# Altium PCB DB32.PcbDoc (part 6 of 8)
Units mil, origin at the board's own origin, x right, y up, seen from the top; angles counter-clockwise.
Board outline 3236.22 x 4456.69 mil, 8 copper layers (Top Layer, MidLayer1, MidLayer2, GND-Layer5, MidLayer3, VCC, MidLayer4, Bottom Layer), stack 61.8 mil thick; 207 components, 474 nets, 1777 pads, 1474 vias.
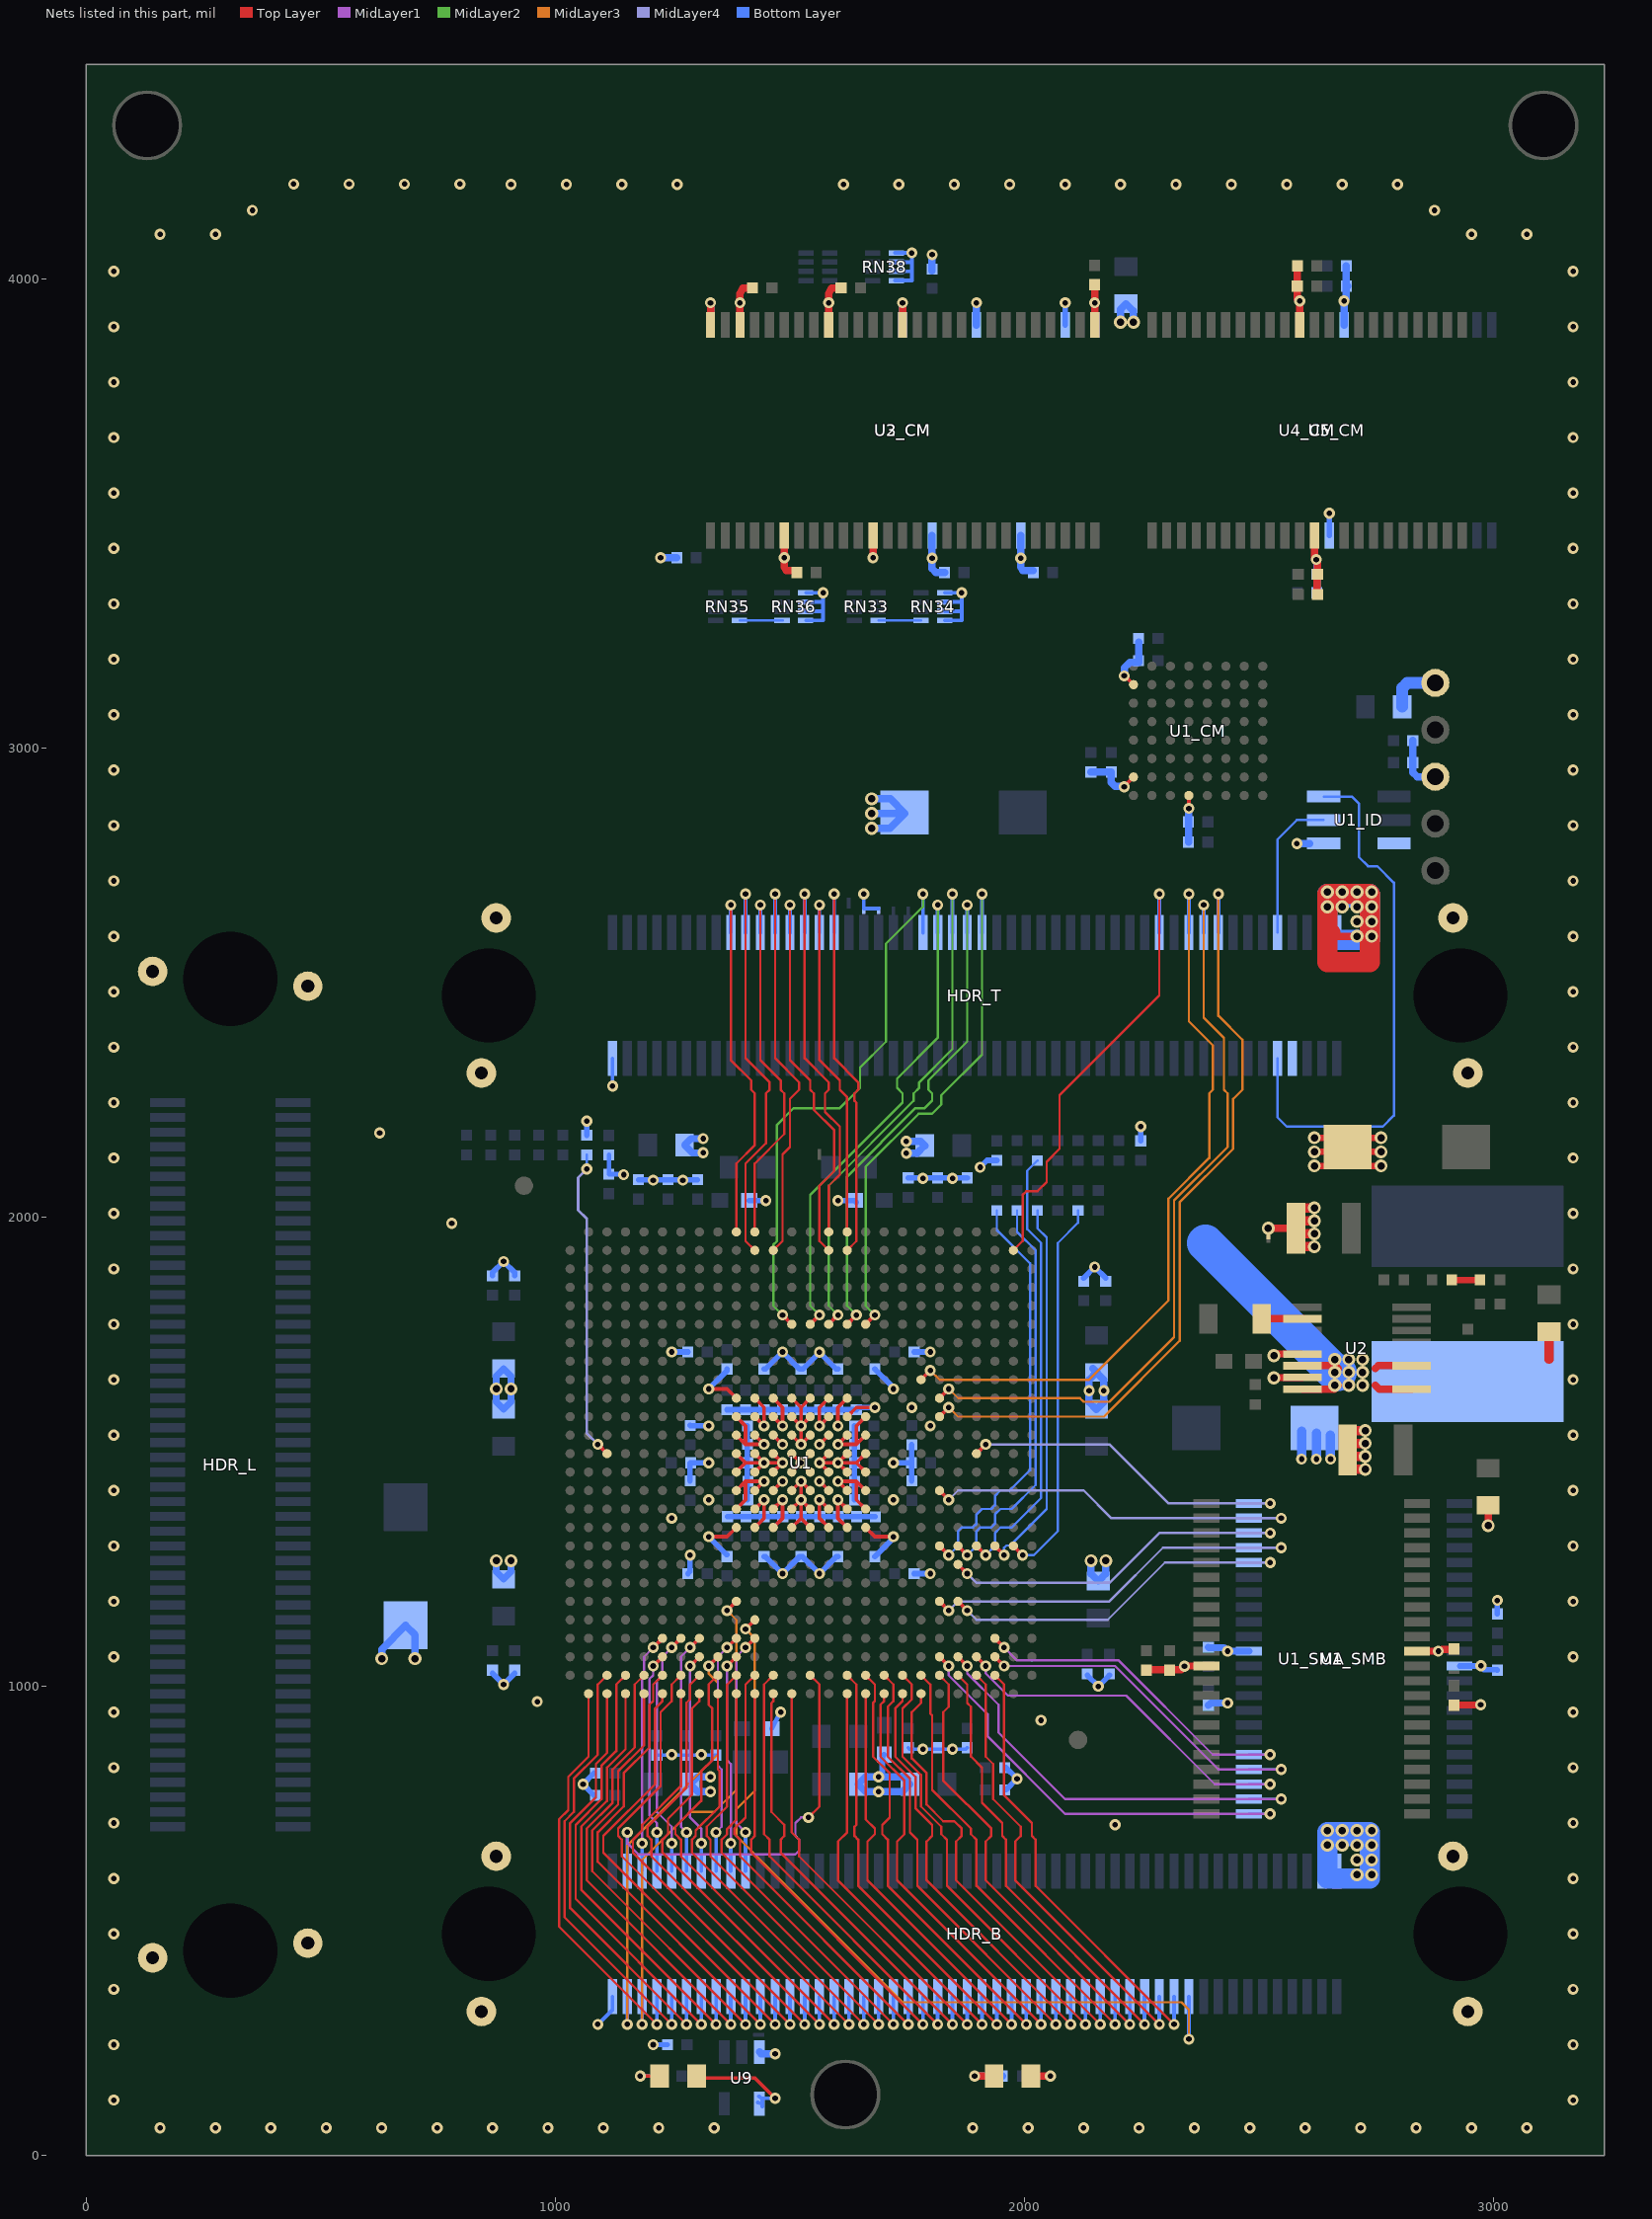
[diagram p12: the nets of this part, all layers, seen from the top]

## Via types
v1: diameter 23.62, hole 11.81, Top Layer to Bottom Layer, 839 vias
v2: diameter 23.62, hole 11.81, Top Layer to Bottom Layer, tented both sides, 499 vias
v3: diameter 27.56, hole 15.75, Top Layer to Bottom Layer, 135 vias
v4: diameter 23.62, hole 11.81, Top Layer to Bottom Layer, tented top, 1 vias

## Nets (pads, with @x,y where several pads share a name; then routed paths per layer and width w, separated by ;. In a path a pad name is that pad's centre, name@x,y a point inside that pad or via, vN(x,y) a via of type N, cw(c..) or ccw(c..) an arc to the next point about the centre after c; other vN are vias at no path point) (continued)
GND: C1_CM.2 C1_FP.2 C1_ID.1 C1_MB.2 C1_PL.2 C1_SMA.2 C1_SMB.2 C2_CM.2 C2_FP.2 C2_ID.2 C2_MB.2 C2_PL.2 C2_SMA.2 C2_SMB.2 C3_CM.2 C3_FP.2 C3_PL.2 C3_SMA.2 C3_SMB.2 C4_CM.2 C4_FP.2 C4_PL.2 C4_SMA.2 C4_SMB.2 C5_CM.2 C5_FP.2 C5_MB.2 C5_PL.2 C6_CM.2 C6_FP.2 C6_PL.2 C7_CM.2 C7_FP.2 C7_PL.2 C8_CM.2 C8_FP.2 C8_PL.2 C9_CM.2 C9_FP.2 C9_PL.2 C10_CM.2 C10_FP.2 C10_PL.2 C11_CM.2 C11_FP.2 C11_PL.2 C12_CM.2 C12_FP.2 C12_PL.2 C13_CM.2 C13_PL.2 C14_CM.2 C14_PL.2 C15.2 C15_CM.2 C15_FP.2 C15_PL.2 C16_CM.2 C16_FP.2 C16_PL.2 C17.2 C17_CM.2 C17_FP.2 C18_CM.2 C18_FP.2 C19.2 C19_CM.2 C19_FP.2 C20.2 C20_CM.2 C20_FP.2 C21_CM.2 C21_FP.2 C22.2 C22_CM.2 C22_FP.2 C23_CM.2 C23_FP.2 C24_CM.2 C24_FP.2 C25_FP.2 C38_FP.2 C39_FP.2 C40_FP.2 C41_FP.2 C42_FP.2 C43_FP.2 C44_FP.2 C45_FP.2 C46_FP.2 C47_FP.2 C48_FP.2 C49_FP.2 C50_FP.2 C51_FP.2 C52_FP.2 C53_FP.2 C54_FP.2 C55_FP.2 C56_FP.2 C62_FP.2 C63_FP.2 C64_FP.2 C65_FP.2 C66_FP.2 C67_FP.2 C68_FP.2 C69_FP.2 C70_FP.2 C71_FP.2 C72_FP.2 C73_FP.2 C74_FP.2 C75_FP.2 C76_FP.2 C77_FP.2 C78_FP.2 C79_FP.2 C80_FP.2 C81_FP.2 C82_FP.2 C83_FP.2 C84_FP.2 C85_FP.2 C86_FP.2 C87_FP.2 C88_FP.2 C89_FP.2 C90_FP.2 C91_FP.2 C92_FP.2 C93_FP.2 C98.1 HDR_B.1 HDR_B.98 HDR_B.100 HDR_B.MH1 HDR_B.MH2 HDR_B.MH3 HDR_B.MH4 HDR_L.MH1 HDR_L.MH2 HDR_L.MH3 HDR_L.MH4 HDR_T.1 HDR_T.98 HDR_T.100 HDR_T.MH1 HDR_T.MH2 HDR_T.MH3 HDR_T.MH4 LED1.2 NT4.2 NT5.2 NT7.2 R5.2 RN34.1 RN34.2 RN34.3 RN34.4 RN36.1 RN36.2 RN36.3 RN36.4 RN38.1 RN38.2 RN38.3 RN38.4 TP0.1 TP2.1 U1.K10 U1.K11 U1.K12 U1.K13 U1.K14 U1.K15 U1.K16 U1.L10 U1.L11 U1.L12 U1.L13 U1.L14 U1.L15 U1.L16 U1.L17 U1.M10 U1.M11 U1.M12 U1.M13 U1.M14 U1.M15 U1.M16 U1.M17 U1.N10 U1.N11 U1.N12 U1.N13 U1.N14 U1.N15 U1.N16 U1.N17 U1.P10 U1.P11 U1.P12 U1.P13 U1.P14 U1.P15 U1.P16 U1.P17 U1.R10 U1.R11 U1.R12 U1.R13 U1.R14 U1.R15 U1.R16 U1.R17 U1.T10 U1.T11 U1.T12 U1.T13 U1.T14 U1.T15 U1.T16 U1.T17 U1.U10 U1.U11 U1.U12 U1.U13 U1.U14 U1.U15 U1.U16 U1.U17 U1_CM.E8 U1_CM.H2 U1_CM.H7 U1_ID.1 U1_SMA.12 U1_SMA.34 U1_SMB.12 U1_SMB.34 U2.13 U2.15 U2_CM.6 U2_CM.12 U2_CM.28 U2_CM.41 U2_CM.46 U2_CM.52 U2_CM.54 U3_CM.6 U3_CM.12 U3_CM.28 U3_CM.41 U3_CM.46 U3_CM.52 U3_CM.54 U4_CM.12 U4_CM.34 U5_CM.12 U5_CM.34 U9.3 | length 14104.8
  Top Layer w7.87: v1(1326.77,1318.9) 1366.14,1318.9 U1.U10@1385.83,1338.58 ; v1(1326.77,1633.86) 1366.14,1633.86 U1.K10@1385.83,1614.17 ; U1.T10@1385.83,1377.95 1405.51,1397.64 1405.51,1437.01 ; U1.R10@1385.83,1417.32 1405.51,1437.01 ; U1.P10@1385.83,1456.69 1405.51,1476.38 ; U1.N10@1385.83,1496.06 1405.51,1476.38 ; U1.M10@1385.83,1535.43 1405.51,1515.75 ; U1.L10@1385.83,1574.8 1405.51,1555.12 1405.51,1515.75 ; U1.U11@1425.2,1338.58 1444.88,1358.27 v1(1444.88,1397.64) U1.T11@1425.2,1377.95 ; U1.R11@1425.2,1417.32 v1(1444.88,1437.01) 1405.51,1437.01 ; U1.P11@1425.2,1456.69 v1(1444.88,1476.38) ; U1.N11@1425.2,1496.06 v1@1444.88,1476.38 ; U1.M11@1425.2,1535.43 v1(1444.88,1515.75) 1405.51,1515.75 ; U1.L11@1425.2,1574.8 v1(1444.88,1555.12) 1444.88,1594.49 U1.K11@1425.2,1614.17 ; U1.U12@1464.57,1338.58 1484.25,1358.27 v1(1484.25,1397.64) U1.T12@1464.57,1377.95 ; U1.R12@1464.57,1417.32 v1(1484.25,1437.01) ; U1.P12@1464.57,1456.69 v1(1484.25,1476.38) ; U1.N12@1464.57,1496.06 v1(1484.25,1476.38) ; U1.M12@1464.57,1535.43 v1(1484.25,1515.75) ; U1.L12@1464.57,1574.8 v1(1484.25,1555.12) 1484.25,1594.49 U1.K12@1464.57,1614.17 ; U1.R13@1503.94,1417.32 v1(1523.62,1437.01) ; U1.P13@1503.94,1456.69 U1.N14@1543.31,1496.06 ; U1.N13@1503.94,1496.06 U1.P14@1543.31,1456.69 ; U1.M13@1503.94,1535.43 v1(1523.62,1515.75) ; U1.L13@1503.94,1574.8 v1(1523.62,1555.12) U1.L14@1543.31,1574.8 ; U1.K13@1503.94,1614.17 1523.62,1594.49 ; U1.U14@1543.31,1338.58 1523.62,1358.27 ; U1.T14@1543.31,1377.95 v1(1523.62,1397.64) ; U1.R14@1543.31,1417.32 v1(1523.62,1437.01) ; U1.M14@1543.31,1535.43 v1(1523.62,1515.75) ; U1.K14@1543.31,1614.17 1523.62,1594.49 ; v1(1562.99,1437.01) U1.R15@1582.68,1417.32 ; v1(1562.99,1515.75) U1.M15@1582.68,1535.43 ; U1.U15@1582.68,1338.58 1562.99,1358.27 v1(1562.99,1397.64) U1.T15@1582.68,1377.95 ; U1.P15@1582.68,1456.69 v1(1562.99,1476.38) ; U1.N15@1582.68,1496.06 v1(1562.99,1476.38) ; U1.L15@1582.68,1574.8 v1(1562.99,1555.12) 1562.99,1594.49 U1.K15@1582.68,1614.17 ; v1(1602.36,1555.12) 1602.36,1594.49 U1.K16@1622.05,1614.17 ; U1.U16@1622.05,1338.58 1602.36,1358.27 v1(1602.36,1397.64) U1.T16@1622.05,1377.95 ; U1.R16@1622.05,1417.32 v1(1602.36,1437.01) 1641.73,1437.01 ; U1.P16@1622.05,1456.69 v1(1602.36,1476.38) ; U1.N16@1622.05,1496.06 v1@1602.36,1476.38 ; U1.M16@1622.05,1535.43 v1(1602.36,1515.75) 1641.73,1515.75 ; U1.L16@1622.05,1574.8 1641.73,1594.49 v1(1681.1,1594.49) ; U1.U17@1661.42,1338.58 1681.1,1318.9 v1(1720.47,1318.9) ; U1.T17@1661.42,1377.95 1641.73,1397.64 1641.73,1437.01 ; U1.R17@1661.42,1417.32 1641.73,1437.01 ; U1.P17@1661.42,1456.69 1641.73,1476.38 ; U1.N17@1661.42,1496.06 1641.73,1476.38 ; U1.M17@1661.42,1535.43 1641.73,1515.75 ; U1.L17@1661.42,1574.8 1641.73,1555.12 1641.73,1515.75 ; v1@2212.6,2918.31 U1_CM.H7@2232.28,2937.99 ; v1@2212.6,3154.53 U1_CM.H2@2232.28,3134.84 ; v1(2350.4,2871.07) U1_CM.E8@2350.39,2898.62 ; 1405.51,1476.38 v1(1444.88,1476.38) ; 1405.51,1476.38 v1@1444.88,1476.38 ; v1@1444.88,1476.38 v1(1484.25,1476.38) ; 1523.62,1358.27 v1(1523.62,1397.64) ; 1523.62,1358.27 U1.U13@1503.94,1338.58 1523.62,1358.27 ; v1(1523.62,1397.64) U1.T13@1503.94,1377.95 v1(1523.62,1397.64) ; v1(1523.62,1397.64) v1(1523.62,1437.01) ; v1(1523.62,1515.75) 1523.62,1594.49 ; v1(1562.99,1476.38) 1641.73,1476.38 ; v1@1602.36,1476.38 1641.73,1476.38
  Top Layer w13.78: v3(2618.11,2109.29) C17.2@2669.08,2109.29 ; v3(2618.11,2139.29) C17.2@2669.08,2139.29 ; v3(2618.11,2169.29) 2669.08,2169.29 C17.2@2689.05,2149.33 C17.2@2673.58,2133.85 ; C17.2@2709.01,2109.29 v3(2759.99,2109.29) ; C17.2@2709.01,2139.29 v3(2759.99,2139.29) ; C17.2@2709.01,2169.29 v3(2759.99,2169.29)
  Top Layer w15: C4_SMA.2@2259.84,1034.45 2260.82,1035.43 2334.65,1035.43 2341,1041.79 v1(2341,1043) 2341.3,1043.3 U1_SMA.34@2387.87,1043.31 ; v3(2531.5,1657.48) 2532.26,1658.25 U2.15@2591.08,1658.25 ; v3(2531.5,1704.72) 2535.43,1708.66 U2.13@2590.55,1708.66 ; U1_SMA.12@2836.69,1074.8 2881.8,1074.8 v1(2882,1075) 2886.02,1075 2889.76,1078.74 2914.47,1078.74 C1_SMA.2@2915.44,1079.71 ; C3_SMA.2@2915.3,957.92 2917.32,957.76 2914.45,960.63 v1(2972.44,960.63)
  Top Layer w15.75: U2_CM.54@1330.71,3901.57 v2(1330.71,3948.82) ; U2_CM.52@1393.7,3901.57 v2(1393.7,3948.82) ; v2@1393.7,3944.88 1393.7,3964.57 ; 1393.7,3968.51 1399.61,3980.32 C7_CM.2@1420.27,3980.31 ; C7_CM.2@1416.34,3980.32 C7_CM.2@1418.31,3978.34 ; U2_CM.6@1488.19,3452.76 1488.19,3409.45 v2(1488.19,3405.51) 1488.19,3385.83 1492.13,3377.95 C10_CM.2@1514.76,3377.95 ; U2_CM.46@1582.68,3901.57 v2(1582.68,3948.82) ; v2@1582.68,3944.88 1582.68,3964.57 1582.68,3968.51 1588.58,3980.32 C8_CM.2@1609.25,3980.31 ; v2(1677.17,3405.51) U2_CM.12@1677.17,3452.76 ; U2_CM.41@1740.16,3901.57 v2(1740.16,3948.82) ; LED1.2@2011.81,169.29 v1(2055.12,169.29) ; U2_CM.28@2149.61,3901.57 C9_CM.2@2149.6,3987.2 ; v3(2519.68,1976.38) C15.2@2582.67,1976.38 ; C16_CM.2@2581.69,4027.55 2581.69,3957.68 v2(2586.61,3952.76) U4_CM.34@2586.61,3901.57 ; U4_CM.12@2618.11,3452.76 2618.11,3405.51 2624.72,3398.9 C17_CM.2@2624.72,3370.07 C17_CM.2@2625.71,3371.06 ; C15_CM.2@2623.74,3329.72 C17_CM.2@2623.74,3370.07 ; 2645.67,2598.43 v3(2708.66,2598.43) ; v3(2988.19,1342.52) C19.2@2988.18,1385.82
  Top Layer w19.68: 2645.67,2551.18 2649.61,2555.12 ; 3118.09,1696.83 C22.2@3118.1,1755.9
  Top Layer w20: C15.2@2578.73,1937 v3(2618.1,1937) ; C15.2@2578.73,1964.56 v3(2618.1,1964.56) ; C15.2@2578.73,1992.12 v3(2618.1,1992.12) ; C15.2@2578.73,2019.68 v3(2618.1,2019.68) ; C20.2@2687.01,1462.59 v3(2726.38,1462.59) ; C20.2@2687.01,1490.15 v3(2726.38,1490.15) ; C20.2@2687.01,1517.71 v3(2726.38,1517.71) ; C20.2@2687.01,1545.27 v3(2726.38,1545.27)
  Top Layer w39.37: 2645.67,2606.3 2653.54,2606.3
  Top Layer w43.31: 2645.67,2547.24 2649.61,2543.31 ; 2645.67,2543.31 2736.22,2543.31 2736.22,2688.98 2645.67,2688.98 2645.67,2543.31
  Bottom Layer w5: v2@1121.06,2278.54 v2(1122.05,2279.53)
  Bottom Layer w7.87: v2(1090.55,279.53) 1122.05,311.02 HDR_B.1@1122.05,338.58 ; v2(1122.05,2279.53) HDR_T.1@1122.05,2338.58 ; C4_PL.2@1216.53,853.34 C2_PL.2@1342.52,853.34 ; RN36.4@1534.64,3271.65 1570.87,3271.65 v1(1570.87,3330.71) RN36.1@1534.64,3330.71 ; RN36.3@1534.64,3291.34 1570.87,3291.34 ; RN36.2@1534.64,3311.02 1570.87,3311.02 ; v2(1657.48,2688.98) 1657.48,2657.48 NT4.2@1688.98,2657.48 ; RN38.4@1723.62,3996.06 1759.84,3996.06 v1(1759.84,4055.12) RN38.1@1723.62,4055.12 ; RN38.3@1723.62,4015.75 1759.84,4015.75 ; RN38.2@1723.62,4035.43 1759.84,4035.43 ; C14_PL.2@1751.97,869.09 1754.92,866.14 1875,866.14 C16_PL.2@1877.95,869.09 ; RN34.4@1829.92,3271.65 1866.14,3271.65 v1(1866.14,3330.71) RN34.1@1829.92,3330.71 ; RN34.3@1829.92,3291.34 1866.14,3291.34 ; RN34.2@1829.92,3311.02 1866.14,3311.02
  Bottom Layer w9.84: C81_FP.2@1114.17,2132.87 C80_FP.2@1114.17,2091.53 1144.69,2091.53 v1(1145.67,2090.55) ; v1(1208.66,236.22) C98.1@1239.17,236.22 ; C1_PL.2@1460.63,909.45 v1(1480.31,944.88)
  Bottom Layer w11.81: C85_FP.2@866.14,1027.56 v2(889.76,1003.94) C84_FP.2@913.39,1027.56 ; C82_FP.2@866.14,1875 866.14,1881.89 v2(889.76,1905.51) 913.38,1881.89 C83_FP.2@913.38,1875 ; R5.2@1066.93,2174.72 v1(1066.93,2204.72) ; C86_FP.2@1082.68,767.71 v2(1059.06,791.34) C87_FP.2@1082.68,814.96 ; C12_PL.2@1177.16,2079.72 C10_PL.2@1303.15,2079.72 ; v1(1248.03,1712.6) C19_FP.2@1282.48,1712.59 ; C4_FP.2@1282.48,1240.16 1287.4,1245.08 v1(1287.4,1279.53) ; C15_FP.2@1287.4,1437.99 1287.4,1475.39 C24_FP.2@1288.38,1476.37 v1@1326.77,1476.37 ; C25_FP.2@1287.4,1556.1 1288.38,1555.12 v1(1326.77,1555.12) ; v1(1326.77,1318.9) 1365.16,1280.51 C16_FP.2@1366.14,1280.51 ; v1(1326.77,1633.86) 1366.14,1673.23 C12_FP.2@1366.14,1676.18 ; C69_FP.2@1366.14,1589.56 C64_FP.2@1641.73,1589.56 1646.65,1594.49 v1(1681.1,1594.49) ; C73_FP.2@1366.82,1361.64 C63_FP.2@1681.78,1361.64 ; C65_FP.2@1409.45,1397.63 C54_FP.2@1409.45,1555.12 ; C9_PL.2@1417.33,2035.43 C9_PL.2@1413.39,2035.43 v1(1448.82,2035.43) ; C5_FP.2@1444.88,1276.57 1447.84,1276.57 v1(1484.25,1240.16) 1520.67,1276.57 1526.58,1276.57 v1(1562.99,1240.16) 1599.41,1276.57 C6_FP.2@1602.36,1276.57 ; C23_FP.2@1444.88,1676.18 1447.83,1676.18 v1(1484.25,1712.6) 1520.67,1676.18 1527.16,1676.18 v1(1562.99,1712.01) 1598.82,1676.18 C22_FP.2@1602.36,1676.18 ; v1(1602.36,2035.43) C5_PL.2@1637.79,2035.43 ; C5_PL.2@1629.92,2035.43 C5_PL.2@1637.79,2035.43 ; C76_FP.2@1637.8,1397.64 C56_FP.2@1637.8,1555.12 ; C5_PL.2@1641.73,2031.49 C5_PL.2@1637.79,2035.43 ; C18_FP.2@1681.1,1276.57 1720.47,1315.95 v1(1720.47,1318.9) ; C10_FP.2@1681.1,1676.18 1720.47,1636.8 v1(1720.47,1633.86) ; v1(1688.98,807.09) 1696.85,814.96 1696.85,850.39 C13_PL.2@1700.78,854.33 ; v1(1720.47,1476.38) C20_FP.2@1758.85,1476.38 ; C6_PL.2@1751.97,2083.66 C8_PL.2@1877.95,2083.66 ; C8_FP.2@1759.84,1437.99 1759.84,1475.39 C20_FP.2@1758.85,1476.37 ; C9_FP.2@1759.84,1514.76 1759.84,1477.36 C20_FP.2@1758.85,1476.37 ; C7_FP.2@1764.76,1240.16 v1(1799.21,1240.16) ; C21_FP.2@1764.76,1712.6 v1(1799.21,1712.6) ; v2(1905.51,2106.3) 1920.27,2121.06 C79_FP.2@1940.94,2121.06 ; C88_FP.2@1960.63,779.53 v2(1984.25,803.15) C89_FP.2@1960.63,826.77 ; U3_CM.52@2086.61,3901.57 v2(2086.61,3948.82) ; C93_FP.2@2125.98,1870.08 v2(2149.61,1893.7) C92_FP.2@2173.23,1870.08 ; C91_FP.2@2133.86,1023.62 v2(2157.48,1000) C90_FP.2@2181.1,1023.62 ; U3_CM.54@2149.61,3901.57 v2(2149.61,3948.82) ; C78_FP.2@2248.03,2162.4 v2(2248.03,2192.91) ; U5_CM.12@2649.61,3452.76 v2(2649.61,3500) ; U1_SMB.34@2927.25,1043.3 v1@2972.3,1043.3 ; v1(2973,1044) v1@2972.3,1043.3 ; C4_SMB.2@3007.87,1034.45 3006.88,1035.43 2979.33,1035.43 2972.3,1042.47 v1@2972.3,1043.3 ; C2_SMB.2@3007.87,1154.53 v1(3007.87,1183.07)
  Bottom Layer w15: C1_MB.2@661.42,1110.59 C1_MB.2@680.83,1130 700.79,1110.04 v3(700.79,1059.06) ; v3(874.02,1267.72) 874.02,1244.09 C41_FP.2@889.76,1228.34 905.51,1244.09 v3(905.51,1267.72) ; v1@1314.96,2137.14 1291.99,2137.14 C38_FP.2@1275.59,2153.54 1289.29,2167.24 v1(1315.08,2167.24) ; v2(1330.71,775.59) 1303.15,775.59 C45_FP.2@1287.4,791.34 1303.15,807.09 v2(1330.71,807.09) ; v1@1748.03,2139.93 1748.03,2132.31 v1(1748.27,2136.26) ; v1(1748.27,2136.26) 1771.23,2136.24 C40_FP.2@1787.52,2152.54 ; C1_SMB.2@2391.82,959.64 2396.75,964.57 v1(2433.07,964.57) ; C3_SMB.2@2391.82,1083.65 2392.8,1082.68 2425.2,1082.68 v1@2432.87,1075 ; v1(2433,1075) 2433.21,1074.79 U1_SMB.12@2478.43,1074.8 ; C1_FP.2@874.02,1606.29 C1_FP.2@889.76,1590.55 905.51,1606.3 905.51,1661.41 C39_FP.2@889.76,1677.16 874.02,1661.42 C1_FP.2@874.02,1606.29 ; C2_FP.2@1645.67,791.34 1661.41,775.59 1740.16,775.59 C44_FP.2@1755.9,791.34 1740.15,807.09 1661.42,807.09 C2_FP.2@1645.67,791.34
  Bottom Layer w15.75: v3(629.92,1059.06) 629.92,1079.09 C1_MB.2@680.83,1130 ; v2(1224.41,3405.51) C13_CM.2@1258.85,3405.51 ; U3_CM.28@1330.71,3901.57 v2@1330.71,3944.88 ; U9.3@1435.04,220.47 1438.97,216.54 v1(1468.5,216.54) ; v3(1674.21,2828.74) 1713.39,2828.74 1745.15,2860.51 1713.93,2891.73 v3(1674.21,2891.73) ; v3(1674.21,2860.24) C2_MB.2@1744.88,2860.24 ; U3_CM.41@1740.16,3901.57 v2(1740.16,3948.82) ; v1(1748.03,2161.42) 1778.65,2161.42 C40_FP.2@1787.52,2152.54 ; U3_CM.12@1803.15,3452.76 1803.15,3405.51 v2(1803.15,3404.53) 1803.15,3381.89 1811.04,3374.01 C12_CM.2@1829.72,3374.01 ; C14_CM.2@1803.15,4016.72 1803.15,4047.24 v2(1803.15,4051.18) ; U3_CM.46@1897.64,3901.57 v2(1897.64,3948.82) v2@1897.64,3944.88 ; U3_CM.6@1992.13,3452.76 1992.13,3385.83 1996.06,3377.95 C11_CM.2@2018.7,3377.95 ; v3(2141.73,1267.72) 2141.73,1240.15 C43_FP.2@2157.48,1224.41 2161.42,1228.35 2173.23,1240.16 v3(2173.23,1267.72) ; C4_CM.2@2141.73,2948.82 C1_CM.2@2185.04,2948.82 2185.04,2926.19 2192.92,2918.31 v1@2212.6,2918.31 ; C42_FP.2@2145.66,1677.16 2169.29,1653.54 2169.29,1606.3 C3_FP.2@2153.54,1590.55 2137.8,1606.29 2137.8,1653.54 C42_FP.2@2153.54,1669.29 ; v3(2204.72,3907.48) 2204.72,3935.04 C24_CM.2@2216.53,3946.84 2232.28,3931.1 v3(2232.28,3907.48) ; v1(2212.6,3153.54) 2212.6,3170.28 2224.41,3182.09 2243.11,3182.09 C6_CM.2@2243.11,3225.39 ; C5_CM.2@2349.4,2799.21 2350.4,2800.2 v1(2350.4,2871.07) ; v2(2580.71,2796.26) 2608.06,2796.26 U1_ID.1@2608.25,2796.45 ; v2(2622.05,3401.57) 2623.03,3400.6 C19_CM.2@2623.03,3330.7 ; v2@2681.1,3956.7 v2(2681.1,3952.76) 2686.02,3957.67 C22_CM.2@2686.02,3984.25 ; U5_CM.34@2681.38,3901.57 v2@2681.38,3944.88 ; C20_CM.2@2686.02,4027.55 2686.02,3987.2 C22_CM.2@2688.98,3984.25 ; C1_ID.1@2827.75,3015.74 2827.75,2947.84 2836.92,2938.67 TP2.1@2875.71,2938.66
  Bottom Layer w20: v1(2590.55,1484.25) C5_MB.2@2590.55,1543.31 ; v1(2622.05,1484.25) C5_MB.2@2622.05,1539.37 ; v1(2652.34,1484.25) C5_MB.2@2652.34,1535.44
  Bottom Layer w25: C23_CM.2@2805.12,3087.59 2805.12,3127.96 2815.83,3138.67 TP0.1@2875.71,3138.67
  Bottom Layer w43.31: v3@2649.61,681.1 v3@2736.22,681.1 ; v3@2649.61,2681.1 v3@2736.22,2681.1 ; v3@2736.22,681.1 2736.22,661.42 2736.22,629.92 2736.22,598.42 2736.22,590.55 2645.67,590.55 2645.67,688.98 2736.22,688.98 v3@2736.22,681.1 ; v3@2736.22,2681.1 2736.22,2661.42 2736.22,2629.92 2736.22,2598.43 2736.22,2590.55 2645.67,2590.55 2645.67,2688.98 2736.22,2688.98 v3@2736.22,2681.1
  other v1: 157.48,59.06 275.59,59.06 393.7,59.06 511.81,59.06 629.92,59.06 748.03,59.06 866.14,59.06 984.25,59.06 1102.36,59.06 1220.47,59.06 1338.58,59.06 1889.76,59.06 2007.87,59.06 2125.98,59.06 2244.09,59.06 2362.2,59.06 2480.31,59.06 2598.43,59.06 2716.54,59.06 2834.65,59.06 2952.76,59.06 3070.87,59.06 59.06,118.11 3169.29,118.11 59.06,236.22 3169.29,236.22 59.06,354.33 3169.29,354.33 59.06,472.44 3169.29,472.44 59.06,590.55 3169.29,590.55 59.06,708.66 3169.29,708.66 1688.98,775.59 59.06,826.77 3169.29,826.77 1783.46,866.14 1846.46,866.14 59.06,944.88 3169.29,944.88 961.57,967.47 59.06,1062.99 3169.29,1062.99 59.06,1181.1 3169.29,1181.1 59.06,1299.21 3169.29,1299.21 1248.03,1358.27 1326.77,1397.64 1720.47,1397.64 59.06,1417.32 3169.29,1417.32 1326.77,1476.38 1523.62,1476.38 59.06,1535.43 3169.29,1535.43 1799.21,1555.12 1759.84,1594.49 2137.8,1629.92 2169.29,1629.92 59.06,1653.54 3169.29,1653.54 59.06,1771.65 3169.29,1771.65 59.06,1889.76 3169.29,1889.76 779.24,1986.9 59.06,2007.87 3169.29,2007.87 1208.66,2078.74 1271.65,2078.74 1783.46,2082.68 1846.46,2082.68 59.06,2125.98 3169.29,2125.98 1315.08,2137.24 625.7,2179.57 59.06,2244.09 3169.29,2244.09 59.06,2362.2 3169.29,2362.2 59.06,2480.31 3169.29,2480.32 59.06,2598.43 3169.29,2598.43 59.06,2716.54 3169.29,2716.54 59.06,2834.65 3169.29,2834.65 2212.6,2917.32 59.06,2952.76 3169.29,2952.76 59.06,3070.87 3169.29,3070.87 59.06,3188.98 3169.29,3188.98 59.06,3307.09 3169.29,3307.09 59.06,3425.2 3169.29,3425.2 59.06,3543.31 3169.29,3543.31 59.06,3661.42 3169.29,3661.42 59.06,3779.53 3169.29,3779.53 59.06,3897.64 3169.29,3897.64 59.06,4015.75 3169.29,4015.75 157.48,4094.49 275.59,4094.49 2952.76,4094.49 3070.87,4094.49 354.33,4145.67 2874.02,4145.67 905.51,4200.79 1023.62,4200.79 1141.73,4200.79 1259.84,4200.79 1614.17,4200.79 1732.28,4200.79 1850.39,4200.79 1968.5,4200.79 2086.61,4200.79 2204.72,4200.79 2322.83,4200.79 2440.94,4200.79 2559.06,4200.79 2677.17,4200.79 2795.28,4200.79 442.21,4201.8 560.32,4201.8 678.43,4201.8 796.54,4201.8
  other v2: 2193.14,704.91 1248.03,854.33 1311.02,854.33 2035.41,927.64 1992.13,3404.53
  other v3: 2708.66,598.42 2740.16,598.42 2708.66,629.92 2740.16,629.92 2645.67,661.42 2677.17,661.42 2708.66,661.42 2740.16,661.42 2645.67,692.91 2677.17,692.91 2708.66,692.91 2740.16,692.91 874.02,1633.86 905.51,1633.86 2740.16,2598.43 2708.66,2629.92 2740.16,2629.92 2645.67,2661.42 2677.17,2661.42 2708.66,2661.42 2740.16,2661.42 2645.67,2692.91 2677.17,2692.91 2708.66,2692.91 2740.16,2692.91
INITN: R8.2 U1.V25 | length 825.3
  Top Layer w7.87: U1.V25@1976.38,1299.21 v1(1996.07,1279.53)
  Bottom Layer w5: v1(1996.07,1279.53) 2019.68,1279.53 2070.87,1330.71 2070.87,1944.88 2114.17,1988.18 R8.2@2114.17,2014.25
IO0: HDR_B.7 U1.AF2 | length 876.3
  Top Layer w5: U1.AF2@1070.87,984.25 1070.87,921.26 1070.87,909.45 1070.87,850.39 1027.56,807.09 1027.56,736.22 1007.87,716.54 1007.87,488.19 v2(1216.54,279.53)
  Bottom Layer w7.87: v2(1216.54,279.53) HDR_B.7@1216.54,338.58
IO1: HDR_B.9 U1.AE3 | length 935.2
  Top Layer w5: U1.AE3@1110.24,1023.62 1090.55,1003.94 1090.55,921.26 1090.55,909.45 1090.55,854.33 1039.37,803.15 1039.37,732.28 1019.68,712.6 1019.68,507.87 v2(1248.03,279.53)
  Bottom Layer w7.87: v2(1248.03,279.53) HDR_B.9@1248.03,338.58
IO2: HDR_B.11 U1.AF3 | length 899.1
  Top Layer w5: U1.AF3@1110.24,984.25 1110.24,921.26 1110.24,909.45 1110.24,858.27 1086.61,834.65 1086.61,763.78 1031.5,708.66 1031.5,527.56 v2(1279.53,279.53)
  Bottom Layer w7.87: v2(1279.53,279.53) HDR_B.11@1279.53,338.58
IO3: HDR_B.13 U1.AE4 | length 958.1
  Top Layer w5: U1.AE4@1149.61,1023.62 1129.92,1003.94 1129.92,983.27 1129.92,941.93 1129.92,921.26 1129.92,909.45 1129.92,862.2 1098.43,830.71 1098.43,759.84 1043.31,704.72 1043.31,547.24 v2(1311.02,279.53)
  Bottom Layer w7.87: v2(1311.02,279.53) HDR_B.13@1311.03,338.58
IO4: HDR_B.15 U1.AF4 | length 922
  Top Layer w5: U1.AF4@1149.61,984.25 1149.61,921.26 1149.61,909.45 1149.61,866.14 1110.24,826.77 1110.24,755.91 1055.12,700.79 1055.12,566.93 v2(1342.52,279.53)
  Bottom Layer w7.87: v2(1342.52,279.53) HDR_B.15@1342.52,338.58
IO5: HDR_B.17 U1.AE5 | length 980.9
  Top Layer w5: U1.AE5@1188.98,1023.62 1169.29,1003.94 1169.29,983.27 1169.29,941.93 1169.29,921.26 1169.29,909.45 1169.29,870.08 1122.05,822.83 1122.05,751.97 1066.93,696.85 1066.93,586.61 v2(1374.02,279.53)
  Bottom Layer w7.87: v2(1374.02,279.53) HDR_B.17@1374.02,338.58
IO6: HDR_B.19 U1.AF5 | length 944.8
  Top Layer w5: U1.AF5@1188.98,984.25 1188.98,921.26 1188.98,909.45 1188.98,874.02 1133.86,818.9 1133.86,748.03 1078.74,692.91 1078.74,606.3 v2(1405.51,279.53)
  Bottom Layer w7.87: v2(1405.51,279.53) HDR_B.19@1405.51,338.58
IO7: HDR_B.21 U1.AE6 | length 1003.7
  Top Layer w5: U1.AE6@1228.35,1023.62 1208.66,1003.94 1208.66,968.5 1200.79,960.63 1200.79,921.26 1200.79,909.45 1200.79,870.08 1145.67,814.96 1145.67,744.09 1090.55,688.98 1090.55,625.98 v2(1437.01,279.53)
  Bottom Layer w7.87: v2(1437.01,279.53) HDR_B.21@1437.01,338.58
IO8: HDR_B.23 U1.AF6 | length 967.6
  Top Layer w5: U1.AF6@1228.35,984.25 1228.35,968.5 1212.6,952.75 1212.6,921.26 1212.6,909.45 1212.6,791.34 1102.36,681.1 1102.36,645.67 v2(1468.5,279.53)
  Bottom Layer w7.87: v2(1468.5,279.53) HDR_B.23@1468.51,338.58
IO9: HDR_B.25 U1.AE7 | length 1010.3
  Top Layer w5: U1.AE7@1267.72,1023.62 1248.03,1003.94 1248.03,968.5 1224.41,944.88 1224.41,921.26 1224.41,909.45 1224.41,787.4 1133.86,696.85 1133.86,681.1 1141.73,673.23 1141.73,637.79 v2(1500,279.53)
  Bottom Layer w7.87: v2(1500,279.53) HDR_B.25@1500,338.58
IO10: HDR_B.27 U1.AF7 | length 957.8
  Top Layer w5: U1.AF7@1267.72,984.25 1267.72,921.26 1267.72,909.45 1267.72,787.4 1185.04,704.72 1185.04,692.91 1165.35,673.23 1165.35,645.67 v2(1531.5,279.53)
  Bottom Layer w7.87: v2(1531.5,279.53) HDR_B.27@1531.5,338.58
IO11: HDR_B.29 U1.AE8 | length 1000.5
  Top Layer w5: U1.AE8@1307.09,1023.62 1287.4,1003.94 1287.4,983.27 1287.4,972.93 1279.53,965.06 1279.53,921.26 1279.53,909.45 1279.53,783.71 1196.85,701.03 1196.85,681.1 1204.72,673.23 1204.72,637.79 v2(1562.99,279.53)
  Bottom Layer w7.87: v2(1562.99,279.53) HDR_B.29@1562.99,338.58
IO12: HDR_B.31 U1.AF8 | length 948.1
  Top Layer w5: U1.AF8@1307.09,984.25 1307.09,968.5 1291.34,952.75 1291.34,921.26 1291.34,909.45 1291.34,768.7 1240.16,717.52 1240.16,685.04 1228.35,673.23 1228.35,645.67 v2(1594.49,279.53)
  Bottom Layer w7.87: v2(1594.49,279.53) HDR_B.31@1594.49,338.58
IO13: HDR_B.33 U1.AE9 | length 1000.5
  Top Layer w5: U1.AE9@1346.46,1023.62 1326.77,1003.94 1326.77,960.63 1334.65,952.76 1334.65,921.26 1334.64,909.45 1334.64,842.52 1311.02,818.9 1311.02,755.91 1255.91,700.79 1255.91,685.04 1267.72,673.23 1267.72,637.79 v2(1625.99,279.53)
  Bottom Layer w7.87: v2(1625.99,279.53) HDR_B.33@1625.99,338.58
IO14: HDR_B.35 U1.AF9 | length 941.5
  Top Layer w5: U1.AF9@1346.46,984.25 1346.46,921.26 1346.46,909.45 1346.46,822.83 1350.39,818.9 1350.39,744.09 1299.21,692.91 1299.21,681.1 1291.34,673.23 1291.34,645.67 v2(1657.48,279.53)
  Bottom Layer w7.87: v2(1657.48,279.53) HDR_B.35@1657.48,338.58
IO15: HDR_B.37 U1.AE10 | length 980.9
  Top Layer w5: U1.AE10@1385.83,1023.62 1366.14,1003.94 1366.14,921.26 1366.14,909.45 1366.14,744.09 1322.83,700.79 1322.83,681.1 1330.71,673.23 1330.71,637.79 v2(1688.98,279.53)
  Bottom Layer w7.87: v2(1688.98,279.53) HDR_B.37@1688.98,338.58
IO16: HDR_B.39 U1.AF10 | length 928.5
  Top Layer w5: U1.AF10@1385.83,984.25 1385.83,921.26 1385.83,909.45 1385.83,715.92 1366.14,696.24 1366.14,685.04 1354.33,673.23 1354.33,645.67 v2(1720.47,279.53)
  Bottom Layer w7.87: v2(1720.47,279.53) HDR_B.39@1720.48,338.58
IO17: HDR_B.41 U1.AE11 | length 974.4
  Top Layer w5: U1.AE11@1425.2,1023.62 1405.51,1003.93 1405.51,921.26 1405.51,909.45 1405.51,720.47 1381.89,696.85 1381.89,685.04 1393.7,673.23 1393.7,637.79 v2(1751.97,279.53)
  Bottom Layer w7.87: v2(1751.97,279.53) HDR_B.41@1751.97,338.58
IO18: HDR_B.43 U1.AF11 | length 918.7
  Top Layer w5: U1.AF11@1425.2,984.25 1425.2,921.26 1425.2,909.45 1425.2,681.1 1417.32,673.23 1417.32,645.67 v2(1783.47,279.53)
  Bottom Layer w7.87: v2(1783.47,279.53) HDR_B.43@1783.47,338.58
IO19: HDR_B.45 U1.AE12 | length 964.6
  Top Layer w5: U1.AE12@1464.57,1023.62 1444.88,1003.94 1444.88,921.26 1444.88,909.45 1444.88,685.04 1456.69,673.23 1456.69,637.79 v2(1814.96,279.53)
  Bottom Layer w7.87: v2(1814.96,279.53) HDR_B.45@1814.96,338.58
IO20: HDR_B.47 U1.AF12 | length 931.8
  Top Layer w5: U1.AF12@1464.57,984.25 1464.57,968.5 1460.63,964.57 1460.63,921.26 1460.63,909.45 1460.63,732.28 1488.19,704.72 1488.19,681.1 1480.31,673.23 1480.31,645.67 v2(1846.46,279.53)
  Bottom Layer w7.87: v2(1846.46,279.53) HDR_B.47@1846.46,338.58
IO21: HDR_B.49 U1.AF13 | length 918.7
  Top Layer w5: U1.AF13@1503.94,984.25 1503.94,921.26 1503.94,909.45 1503.94,688.98 1519.69,673.23 1519.69,637.79 v2(1877.95,279.53)
  Bottom Layer w7.87: v2(1877.95,279.53) HDR_B.49@1877.96,338.58
IO22: HDR_B.51 U1.AF16 | length 899.1
  Top Layer w5: U1.AF16@1622.05,984.25 1622.05,921.26 1622.05,909.45 1622.05,688.98 1602.36,669.29 1602.36,586.61 v2(1909.45,279.53)
  Bottom Layer w7.87: v2(1909.45,279.53) HDR_B.51@1909.45,338.58
IO23: HDR_B.53 U1.AE16 | length 938.5
  Top Layer w5: U1.AE16@1622.05,1023.62 1641.73,1003.93 1641.73,921.26 1641.73,909.45 1641.73,704.72 1637.8,700.79 1637.8,681.1 1645.67,673.23 1645.67,574.8 v2(1940.95,279.53)
  Bottom Layer w7.87: v2(1940.95,279.53) HDR_B.53@1940.95,338.58
IO24: HDR_B.55 U1.AF17 | length 905.7
  Top Layer w5: U1.AF17@1661.42,984.25 1661.42,921.26 1661.42,909.45 1661.42,716.54 1681.1,696.85 1681.1,685.04 1665.35,669.29 1665.35,586.61 v2(1972.44,279.53)
  Bottom Layer w7.87: v2(1972.44,279.53) HDR_B.55@1972.44,338.58
IO25: HDR_B.57 U1.AE17 | length 961.3
  Top Layer w5: U1.AE17@1661.42,1023.62 1681,1004.04 1681,968.4 1677.17,964.57 1677.17,921.26 1677.17,909.45 1677.17,850.39 1712.6,814.96 1712.6,720.47 1696.85,704.72 1696.85,685.04 1708.66,673.23 1708.66,574.8 v2(2003.94,279.53)
  Bottom Layer w7.87: v2(2003.94,279.53) HDR_B.57@2003.94,338.58
IO26: HDR_B.59 U1.AF18 | length 922
  Top Layer w5: U1.AF18@1700.79,984.25 1700.79,968.5 1692.91,960.63 1692.91,921.26 1692.91,909.45 1692.91,850.39 1744.09,799.21 1744.09,685.04 1728.35,669.29 1728.35,586.61 v2(2035.43,279.53)
  Bottom Layer w7.87: v2(2035.43,279.53) HDR_B.59@2035.44,338.58
IO27: HDR_B.61 U1.AE18 | length 964.6
  Top Layer w5: U1.AE18@1700.79,1023.62 1720.47,1003.94 1720.47,968.5 1708.66,956.69 1708.66,921.26 1708.66,909.45 1708.66,850.39 1755.91,803.15 1755.91,688.98 1771.65,673.23 1771.65,574.8 v2(2066.93,279.53)
  Bottom Layer w7.87: v2(2066.93,279.53) HDR_B.61@2066.93,338.58
IO28: HDR_B.63 U1.AF19 | length 935
  Top Layer w5: U1.AF19@1740.16,984.25 1740.16,968.51 1724.41,952.76 1724.41,921.26 1724.41,909.45 1724.41,850.39 1767.72,807.09 1767.72,740.16 1803.15,704.72 1803.15,681.1 1791.34,669.29 1791.34,586.61 v2(2098.43,279.53)
  Bottom Layer w7.87: v2(2098.43,279.53) HDR_B.63@2098.43,338.58
IO29: HDR_B.65 U1.AE19 | length 980.9
  Top Layer w5: U1.AE19@1740.16,1023.62 1759.84,1003.94 1759.84,972.44 1740.16,952.76 1740.16,921.26 1740.16,909.45 1740.16,850.39 1779.53,811.02 1779.53,744.09 1822.83,700.79 1822.83,685.04 1834.65,673.23 1834.65,574.8 v2(2129.92,279.53)
  Bottom Layer w7.87: v2(2129.92,279.53) HDR_B.65@2129.92,338.58
IO30: HDR_B.67 U1.AF20 | length 961.9
  Top Layer w5: U1.AF20@1779.53,984.25 1779.53,964.57 1759.84,944.88 1759.84,921.26 1759.84,909.45 1759.84,846.46 1791.34,814.96 1791.34,748.03 1826.77,712.6 1850.39,712.6 1866.14,696.85 1866.14,681.1 1854.33,669.29 1854.33,586.61 v2(2161.42,279.53)
  Bottom Layer w7.87: v2(2161.42,279.53) HDR_B.67@2161.42,338.58
IO31: HDR_B.69 U1.AE20 | length 974.4
  Top Layer w5: U1.AE20@1779.53,1023.62 1799.21,1003.94 1799.21,941.93 1803.15,937.99 1803.15,921.26 1803.15,909.45 1803.15,779.53 1885.83,696.85 1885.83,685.04 1897.64,673.23 1897.64,574.8 v2(2192.91,279.53)
  Bottom Layer w7.87: v2(2192.91,279.53) HDR_B.69@2192.92,338.58
IO32: HDR_B.71 U1.AE21 | length 990.8
  Top Layer w5: U1.AE21@1818.9,1023.62 1838.58,1003.94 1838.58,983.27 1838.58,956.69 1826.77,944.88 1826.77,921.26 1826.59,909.45 1826.59,799.4 1929.13,696.85 1929.13,681.1 1917.32,669.29 1917.32,586.61 v2(2224.41,279.53)
  Bottom Layer w7.87: v2(2224.41,279.53) HDR_B.71@2224.41,338.58
IO33: HDR_B.73 U1.AE22 | length 967.8
  Top Layer w5: U1.AE22@1858.27,1023.62 1877.95,1003.93 1877.95,964.57 1885.83,956.69 1885.83,921.26 1886.07,909.69 1886.07,850.15 1909.45,826.77 1909.45,751.97 1952.75,708.66 1952.75,681.1 1960.63,673.23 1960.63,574.8 v2(2255.91,279.53)
  Bottom Layer w7.87: v2(2255.91,279.53) HDR_B.73@2255.91,338.58
IO34: HDR_B.75 U1.AE23 | length 974.4
  Top Layer w5: U1.AE23@1897.64,1023.62 1917.32,1003.94 1917.32,921.26 1917.32,909.45 1917.32,850.39 1933.07,834.65 1933.07,759.84 1992.12,700.79 1992.12,681.1 1980.31,669.29 1980.31,586.61 v2(2287.4,279.53)
  Bottom Layer w7.87: v2(2287.4,279.53) HDR_B.75@2287.41,338.58
IO35: HDR_B.77 U1.AE24 | length 961.3
  Top Layer w5: U1.AE24@1937.01,1023.62 1956.69,1003.94 1956.69,988.19 1956.69,921.26 1956.69,909.45 1956.69,767.72 2015.75,708.66 2015.75,681.1 2023.62,673.23 2023.62,574.8 v2(2318.9,279.53)
  Bottom Layer w7.87: v2(2318.9,279.53) HDR_B.77@2318.9,338.58
KBCLOCK: HDR_T.26 U1.B15 | length 855.8
  Top Layer w5: v2(1500,2665.35) 1500,2334.64 1543.31,2291.34 1543.31,2271.65 1551.18,2263.78 1551.18,2228.35 1594.49,2185.04 1594.49,2098.43 1562.5,2066.44 1562.5,2042.32 1562.99,2031.5 1562.99,1948.82 U1.B15@1582.68,1929.13
  Bottom Layer w7.87: HDR_T.26@1500,2606.3 v2(1500,2665.35)
KBDATA: HDR_T.28 U1.A15 | length 850.5
  Top Layer w5: v2(1531.5,2688.98) 1531.49,2338.58 1582.68,2287.4 1582.68,2271.65 1574.8,2263.78 1574.8,2224.41 1606.3,2192.91 1606.3,2090.55 1582.68,2066.93 1582.68,2043.31 1582.68,2031.49 U1.A15@1582.68,1968.5
  Bottom Layer w7.87: HDR_T.28@1531.5,2606.3 v2(1531.5,2688.98)
LED0: HDR_B.6 U1.AC6 | length 514
  Top Layer w7.87: v1(1208.66,1082.68) U1.AC6@1228.35,1102.36
  MidLayer1 w5: v2(1185.04,665.35) 1185.04,909.45 1185.04,921.26 1185.04,1019.68 1188.98,1023.62 1188.98,1062.99 v1(1208.66,1082.68)
  Bottom Layer w7.87: HDR_B.6@1185.04,606.3 v2(1185.04,665.35)
LED1: HDR_B.8 U1.AD6 | length 474.6
  Top Layer w7.87: v1(1208.66,1043.31) U1.AD6@1228.35,1062.99
  MidLayer1 w5: v1(1208.66,1043.31) 1208.66,1023.62 1200.79,1015.75 1200.79,921.26 1200.79,909.45 1200.79,724.41 1216.54,708.66 v2(1216.54,688.98)
  Bottom Layer w7.87: HDR_B.8@1216.54,606.3 v2(1216.54,688.98)
LED2: HDR_B.10 U1.AC7 | length 530.3
  Top Layer w7.87: v1(1248.03,1082.68) U1.AC7@1267.72,1102.36
  MidLayer1 w5: v2(1248.03,665.35) 1248.03,700.79 1216.54,732.28 1216.54,909.45 1216.54,921.26 1216.54,1011.81 1228.35,1023.62 1228.35,1062.99 v1(1248.03,1082.68)
  Bottom Layer w7.87: HDR_B.10@1248.03,606.3 v2(1248.03,665.35)
LED3: HDR_B.12 U1.AC8 | length 517.3
  Top Layer w7.87: v1(1287.4,1082.68) U1.AC8@1307.09,1102.36
  MidLayer1 w5: v2(1279.53,688.98) 1267.72,700.79 1267.72,909.45 1267.72,921.26 1267.72,1062.99 v1(1287.4,1082.68)
  Bottom Layer w7.87: HDR_B.12@1279.53,606.3 v2(1279.53,688.98)
LED4: HDR_B.14 U1.AD8 | length 474.6
  Top Layer w7.87: v1(1287.4,1043.31) U1.AD8@1307.09,1062.99
  MidLayer1 w5: v1(1287.4,1043.31) 1287.4,921.26 1287.4,909.45 1287.4,720.47 1311.02,696.85 v2(1311.02,665.35)
  Bottom Layer w7.87: HDR_B.14@1311.03,606.3 v2(1311.02,665.35)
LED5: HDR_B.16 U1.AC10 | length 520.5
  Top Layer w7.87: v1(1366.14,1082.68) U1.AC10@1385.83,1102.36
  MidLayer1 w5: v2(1342.52,688.98) 1354.33,700.79 1354.33,822.83 1346.46,830.71 1346.46,909.45 1346.46,921.26 1346.46,1062.99 v1(1366.14,1082.68)
  Bottom Layer w7.87: HDR_B.16@1342.52,606.3 v2(1342.52,688.98)
LED6: HDR_B.18 U1.AD10 | length 468.1
  Top Layer w7.87: v1(1366.14,1043.3) U1.AD10@1385.83,1062.99
  MidLayer1 w5: v1(1366.14,1043.3) 1366.14,921.26 1366.14,909.45 1366.14,842.52 1374.02,834.65 v2(1374.02,665.35)
  Bottom Layer w7.87: HDR_B.18@1374.02,606.3 v2(1374.02,665.35)
LED7: HDR_B.20 U1.AC11 | length 520.5
  Top Layer w7.87: v1(1405.51,1082.68) U1.AC11@1425.2,1102.36
  MidLayer1 w5: v2(1405.51,688.98) 1385.83,708.66 1385.83,909.45 1385.83,921.26 1385.83,1062.99 v1(1405.51,1082.68)
  Bottom Layer w7.87: HDR_B.20@1405.51,606.3 v2(1405.51,688.98)
LED_PGM: LED2.2 U9.4 | length 255.9
  Top Layer w7.87: LED2.2@1295.28,165.35 1301.18,165.35 1425.2,165.35 v1(1468.5,122.05)
  Bottom Layer w7.87: U9.4@1431.51,112.95 1435.5,111.55 U9.4@1440.94,109.65 ; U9.4@1433.07,125.98 1435.04,125.98 1438.97,122.05 v1(1468.5,122.05) ; U9.4@1440.94,104.33 U9.4@1440.94,109.65 ; U9.4@1440.94,122.05 1440.94,110.24 U9.4@1440.94,109.65
LED_PWR: LED1.1 R19.2 | length 102.8
  Top Layer w15.75: v1(1893.7,169.29) LED1.1@1935.04,169.29 LED1.1@1937.01,169.29
  Bottom Layer w15.75: v1(1893.7,169.29) R19.2@1953.23,169.29
LX: L1_PS.1 U2.1 U2.3 U2.14 U2.16 | length 719.2
  Top Layer w15.75: U2.16@2592.58,1633.25 2660.81,1633.25 v3@2669.29,1641.73 ; U2.14@2592.58,1683.25 2651.4,1683.25 ; 2653.54,1681.1 2651.4,1683.25 ; v3@2669.29,1677.17 2663.21,1683.25 2651.4,1683.25 ; 2748.03,1641.73 2756.52,1633.25 U2.1@2824.58,1633.25 ; 2748.03,1677.17 2754.11,1683.25 U2.3@2824.58,1683.25
  Bottom Layer w78.74: 2385.83,1944.88 v3(2661.42,1669.29) v3@2669.29,1669.29
  other v3: 2661.42,1641.73 2690.96,1641.73 2720.5,1641.73 2690.96,1669.29 2720.5,1669.29 2661.42,1696.85 2690.96,1696.85 2720.5,1696.85
M0: R23.2 U1.V23 | length 952.8
  Top Layer w7.87: U1.V23@1897.64,1299.21 v1(1917.33,1279.53)
  Bottom Layer w5: v1(1917.33,1279.53) 1937.01,1299.21 1937.01,1326.77 1948.82,1338.58 1972.44,1338.58 2035.43,1401.57 2035.43,1944.88 2005.91,1974.41 2005.91,2098.9 R23.2@2027.55,2120.55
M1: R18.2 U1.V21 | length 900.6
  Top Layer w7.87: U1.V21@1818.9,1299.21 v1(1838.59,1279.53)
  Bottom Layer w5: v1(1838.59,1279.53) 1858.27,1299.21 1858.27,1330.71 1866.14,1338.58 1889.76,1338.58 1897.64,1346.46 1897.64,1366.14 1909.45,1377.95 1929.13,1377.95 1937.01,1385.83 1937.01,1405.51 1948.82,1417.32 1968.5,1417.32 2011.81,1460.63 2011.81,1901.57 1940.94,1972.44 R18.2@1940.94,2014.25
M2: R28.2 U1.V24 | length 812.8
  Top Layer w7.87: U1.V24@1937.01,1299.21 v1(1956.7,1279.53)
  Bottom Layer w5: v1(1956.7,1279.53) 1956.7,1295.28 1961.65,1300.23 1969.52,1300.23 2047.24,1377.95 2047.24,1956.69 2027.55,1976.38 R28.2@2027.55,2014.25
MOUSECLOCK: HDR_T.30 U1.A16 | length 780.4
  Top Layer w5: v2(1562.99,2665.35) 1562.99,2334.64 1606.3,2291.34 1606.3,2271.65 1622.05,2255.9 1622.05,2043.31 1622.05,2031.5 U1.A16@1622.05,1968.5
  Bottom Layer w7.87: HDR_T.30@1562.99,2606.3 v2(1562.99,2665.35)
MOUSEDATA: HDR_T.32 U1.B16 | length 876.8
  Top Layer w5: v2(1594.49,2688.98) 1594.49,2338.58 1645.67,2287.4 1645.67,2271.65 1637.8,2263.78 1637.8,2248.03 1641.73,2244.09 1641.73,2043.31 1641.73,2031.5 1641.73,1948.82 U1.B16@1622.05,1929.13
  Bottom Layer w7.87: HDR_T.32@1594.49,2606.3 v2(1594.49,2688.98)
NetLED2_1: LED2.1 R21.2 | length 87.1
  Top Layer w7.87: v1(1181.1,169.29) LED2.1@1222.44,169.29
  Bottom Layer w7.87: v1(1181.1,169.29) R21.2@1226.85,169.29
NetR5_1: R5.1 U1.N3 | length 669.4
  Top Layer w7.87: v1(1090.55,1515.75) U1.N3@1110.24,1496.06
  MidLayer4 w5.98: v1(1066.93,2102.36) 1048.68,2084.11 1048.68,2014.83 1066.93,1996.58 1066.93,1539.37 v1(1090.55,1515.75)
  Bottom Layer w5.98: v1(1066.93,2102.36) R5.1@1066.93,2132.36
NetR15_2: R15.2 R16.1 | length 60
  Top Layer w13.78: R15.2@2910.94,1866.14 R16.1@2970.94,1866.14
NetRN33_8: RN33.8 RN34.5 | length 91.3
  Bottom Layer w5: RN33.8@1688.58,3271.65 RN34.5@1779.53,3271.65 RN34.5@1779.92,3271.65
NetRN35_8: RN35.8 RN36.5 | length 91.3
  Bottom Layer w5: RN35.8@1393.3,3271.65 RN36.5@1483.28,3271.66 RN36.5@1484.64,3271.65
NEXUS_TCK: HDR_T.82 U1.K21 | length 1625.5
  Top Layer w7.87: U1.K21@1818.9,1614.17 v1(1838.59,1633.86)
  MidLayer3 w5: v1(1838.59,1633.86) 1858.27,1614.17 2078.74,1614.17 2090.55,1614.17 2118.11,1614.17 2125.98,1606.3 2181.1,1606.3 2318.9,1744.09 2318.9,2035.43 2433.07,2149.61 2433.07,2263.78 2425.2,2271.65 2425.2,2381.89 2381.89,2425.2 v2(2381.89,2665.35)
  Bottom Layer w7.87: HDR_T.82@2381.89,2606.3 v2(2381.89,2665.35)
NEXUS_TDI: HDR_T.84 U1.L21 | length 1707.1
  Top Layer w7.87: U1.L21@1818.9,1574.8 v1(1838.59,1594.49)
  MidLayer3 w5: v1(1838.59,1594.49) 1858.27,1574.8 2078.74,1574.8 2090.55,1574.8 2169.29,1574.8 2330.71,1736.22 2330.71,2031.5 2444.88,2145.67 2444.88,2251.97 2464.57,2271.65 2464.57,2377.95 2413.38,2429.13 v2(2413.38,2688.98)
  Bottom Layer w7.87: HDR_T.84@2413.39,2606.3 v2(2413.38,2688.98)
NEXUS_TDO: HDR_T.76 U1.B25 | length 985.2
  Top Layer w5: U1.B25@1976.38,1929.13 1996.06,1948.82 1996.06,2031.5 1996.06,2043.31 1996.06,2047.24 2003.94,2055.12 2027.56,2055.12 2047.24,2074.8 2047.24,2118.11 2074.8,2145.67 2074.8,2259.84 2086.61,2271.65 2287.4,2472.44 v2(2287.4,2688.98)
  Bottom Layer w7.87: HDR_T.76@2287.4,2606.3 v2(2287.4,2688.98)
NEXUS_TMS: HDR_T.80 U1.J20 | length 1623.1
  Top Layer w7.87: U1.J20@1779.53,1653.54 v1(1799.21,1673.23)
  MidLayer3 w5: v1(1799.21,1673.23) 1818.9,1653.54 2078.74,1653.54 2090.55,1653.54 2137.8,1653.54 2307.09,1822.83 2307.09,2039.37 2393.7,2125.98 2393.7,2263.78 2401.57,2271.65 2401.57,2366.14 2350.39,2417.33 v2(2350.39,2688.98)
  Bottom Layer w7.87: HDR_T.80@2350.4,2606.3 v2(2350.39,2688.98)
ONE_WIRE.PIO2: U1_ID.6
ONE_WIRE_DB_PB: HDR_B.79 U1.AB11 | length 1764.6
  Top Layer w7.87: v1(1405.51,1122.05) U1.AB11@1425.2,1141.73
  MidLayer3 w5: v1(1405.51,1122.05) 1425.2,1102.36 1425.2,921.26 1425.2,909.45 1425.2,777.56 1385.83,738.19 1385.83,681.1 1740.16,326.77 2334.65,326.77 2350.39,311.02 v2(2350.39,248.03)
  Bottom Layer w7.87: v2(2350.39,248.03) HDR_B.79@2350.4,338.58
ONE_WIRE_DBID: HDR_T.92 U1_ID.2 | length 314.2
  Bottom Layer w5: HDR_T.92@2539.37,2606.3 2539.37,2678.98 2539.37,2805.12 2580.71,2846.46 U1_ID.2@2637.59,2846.45
ONE_WIRE_PIO1: HDR_T.91 U1_ID.3 | length 1180.9
  Bottom Layer w5: HDR_T.91@2539.37,2338.58 2539.37,2212.6 2559.06,2192.91 2763.78,2192.91 2787.4,2216.54 2787.4,2712.6 2751.97,2748.03 2732.28,2748.03 2712.6,2767.72 2712.6,2881.89 2698.04,2896.45 U1_ID.3@2637.59,2896.45
PROGRAMN: R24.2 U1.V22 | length 870.8
  Top Layer w7.87: U1.V22@1858.27,1299.21 v1(1877.96,1279.53)
  Bottom Layer w5: v1@1881.89,1279.53 v1(1877.96,1279.53) 1897.64,1299.21 1897.64,1330.71 1905.51,1338.58 1929.13,1338.58 1937.01,1346.46 1937.01,1366.14 1948.82,1377.95 1972.44,1377.95 2023.62,1429.13 2023.62,1929.13 1984.25,1968.51 R24.2@1984.25,2014.25
REF_1V2: C21.2 U2.10 | length 86.8
  Top Layer w15.75: C21.2@2505.9,1783.46 2506.11,1783.25 U2.10@2592.58,1783.25
REF_CLK: HDR_B.4 U1.AE14 | length 901.3
  Top Layer w5: v1(1539.37,720.47) 1562.99,744.09 1562.99,1003.94 U1.AE14@1543.31,1023.62
  MidLayer1 w5: v2(1153.54,688.98) 1153.54,665.35 1177.17,641.73 1511.81,641.73 1519.68,649.61 1519.68,673.23 1511.81,681.1 1511.81,708.66 1523.62,720.47 v1(1539.37,720.47)
  Bottom Layer w7.87: HDR_B.4@1153.55,606.3 v2(1153.54,688.98)
RS232_CTS: HDR_T.22 U1.A11 | length 803.2
  Top Layer w5: U1.A11@1425.2,1968.5 1425.2,2031.5 1425.2,2043.31 1425.2,2114.17 1488.19,2177.16 1488.19,2263.78 1480.31,2271.65 1480.31,2291.34 1437.01,2334.64 v2(1437.01,2665.35)
  Bottom Layer w7.87: HDR_T.22@1437.01,2606.3 v2(1437.01,2665.35)
RS232_RTS: HDR_T.18 U1.A10 | length 793.4
  Top Layer w5: v2(1374.01,2665.35) 1374.02,2334.65 1417.32,2291.34 1417.32,2271.65 1425.2,2263.78 1425.2,2153.54 1385.83,2114.17 1385.83,2043.31 1385.83,2031.5 U1.A10@1385.83,1968.5
  Bottom Layer w7.87: HDR_T.18@1374.02,2606.3 v2(1374.01,2665.35)
RS232_RX: HDR_T.24 U1.B12 | length 886.5
  Top Layer w5: U1.B12@1464.57,1929.13 1484.25,1948.82 1484.25,2031.5 1484.25,2043.31 1484.25,2133.86 1500,2149.61 1500,2251.97 1519.68,2271.65 1519.68,2287.4 1468.5,2338.58 v2(1468.5,2688.98)
  Bottom Layer w7.87: HDR_T.24@1468.5,2606.3 v2(1468.5,2688.98)
RS232_TX: HDR_T.20 U1.B11 | length 893.1
  Top Layer w5: v2(1405.51,2688.98) 1405.51,2338.58 1456.69,2287.4 1456.69,2271.65 1448.82,2263.78 1448.82,2157.48 1405.51,2114.17 1405.51,2043.31 1405.51,2031.5 1405.51,1948.82 U1.B11@1425.2,1929.13
  Bottom Layer w7.87: HDR_T.20@1405.51,2606.3 v2(1405.51,2688.98)
SCL: HDR_B.5 U1.AA10 | length 1090.1
  Top Layer w7.87: v1(1366.14,1161.42) U1.AA10@1385.83,1181.1
  MidLayer3 w5: v2(1185.04,279.53) 1185.04,629.92 1287.4,732.28 1338.58,732.28 1385.83,779.53 1385.83,909.45 1385.83,921.26 1385.83,1141.73 v1(1366.14,1161.42)
  Bottom Layer w7.87: v2(1185.04,279.53) HDR_B.5@1185.04,338.58
SDA: HDR_B.3 U1.AD9 | length 938.7
  Top Layer w7.87: v1(1326.77,1043.31) U1.AD9@1346.46,1062.99
  MidLayer3 w5: v2(1153.54,279.53) 1153.54,661.42 1346.46,854.33 1346.46,909.45 1346.46,921.26 1346.46,1007.87 1326.77,1027.56 v1(1326.77,1043.31)
  Bottom Layer w7.87: v2(1153.54,279.53) HDR_B.3@1153.55,338.58
SLEEP_N: HDR_T.93
SPI_CLK: HDR_T.46 U1.F14 | length 1091.4
  Top Layer w7.87: U1.F14@1543.31,1771.65 v1(1562.99,1791.34)
  MidLayer2 w5: v1(1562.99,1791.34) 1543.31,1811.03 1543.31,2031.5 1543.31,2043.31 1543.31,2047.24 1740.16,2244.09 1740.16,2263.78 1728.35,2275.59 1728.35,2295.28 1814.96,2381.89 v2(1814.96,2665.35)
  Bottom Layer w7.87: HDR_T.46@1814.96,2606.3 v2(1814.96,2665.35)
SPI_DIN: HDR_T.44 U1.F13 | length 1206.1
  Top Layer w7.87: v1(1484.25,1791.34) U1.F13@1503.94,1771.65
  MidLayer2 w5: v1(1484.25,1791.34) 1464.57,1811.02 1464.57,1866.14 1464.57,1893.7 1464.57,1940.95 1472.44,1948.82 1472.44,2031.5 1472.44,2043.31 1472.44,2196.85 1507.87,2232.28 1606.3,2232.28 1646.13,2272.11 1649.61,2275.59 1649.61,2318.9 1704.72,2374.02 1704.72,2582.68 1783.46,2661.42 v2(1783.46,2688.98)
  Bottom Layer w7.87: HDR_T.44@1783.47,2606.3 v2(1783.46,2688.98)
SPI_DOUT: HDR_T.50 U1.F16 | length 1093.1
  Top Layer w7.87: U1.F16@1622.05,1771.65 v1(1641.73,1791.34)
  MidLayer2 w5: v1(1641.73,1791.34) 1622.05,1811.02 1622.05,2031.49 1622.05,2043.31 1622.05,2086.61 1767.72,2232.28 1787.4,2232.28 1803.15,2248.03 1803.15,2263.78 1795.28,2271.65 1795.28,2291.34 1877.95,2374.01 v2(1877.95,2665.35)
  Bottom Layer w7.87: HDR_T.50@1877.95,2606.3 v2(1877.95,2665.35)
SPI_MODE: HDR_T.52 U1.F17 | length 1135.8
  Top Layer w7.87: U1.F17@1661.42,1771.65 v1(1681.1,1791.34)
  MidLayer2 w5: v1(1681.1,1791.34) 1661.42,1811.02 1661.42,2031.49 1661.42,2039.37 1661.42,2107.28 1774.61,2220.47 1803.15,2220.47 1822.83,2240.16 1822.83,2259.84 1909.45,2346.46 v2(1909.45,2688.98)
  Bottom Layer w7.87: HDR_T.52@1909.45,2606.3 v2(1909.45,2688.98)
SPI_SEL: HDR_T.48 U1.F15 | length 1125.6
  Top Layer w7.87: U1.F15@1582.68,1771.65 v1(1602.36,1791.34)
  MidLayer2 w5: v1(1602.36,1791.34) 1582.68,1811.02 1582.68,2031.49 1582.62,2043.31 1582.62,2066.87 1763.78,2248.03 1763.78,2263.78 1775.59,2275.59 1775.59,2287.4 1846.46,2358.27 v2(1846.46,2688.98)
  Bottom Layer w7.87: HDR_T.48@1846.46,2606.3 v2(1846.46,2688.98)
SRAM1_A0: U1.AD21 U1_SMB.1 | length 927.7
  Top Layer w7.87: U1.AD21@1818.9,1062.99 v1(1838.58,1043.31)
  MidLayer1 w5: v1(1838.58,1043.31) 1838.58,1023.62 1921.26,940.95 1921.26,921.26 1921.26,909.45 1921.26,893.7 2086.61,728.35 v1(2523.62,728.35)
  Bottom Layer w5: U1_SMB.1@2478.43,728.35 v1(2523.62,728.35)
SRAM1_A1: U1.AD22 U1_SMB.2 | length 927.2
  Top Layer w7.87: U1.AD22@1858.27,1062.99 v1(1877.95,1043.31)
  MidLayer1 w5: v1(1877.95,1043.31) 1877.95,1027.56 1944.88,960.63 1944.88,921.26 1944.88,909.45 1944.88,901.57 2086.61,759.84 v1(2547.24,759.84)
  Bottom Layer w5: U1_SMB.2@2478.43,759.84 v1(2547.24,759.84)
SRAM1_A2: U1.AD23 U1_SMB.3 | length 792.9
  Top Layer w7.87: U1.AD23@1897.64,1062.99 v1(1917.32,1043.31)
  MidLayer1 w5: v1(1917.32,1043.31) 1917.32,1027.56 1964.57,980.32 2078.74,980.32 2090.55,980.32 2216.54,980.32 2405.51,791.34 v1(2523.62,791.34)
  Bottom Layer w5: U1_SMB.3@2478.43,791.34 v1(2523.62,791.34)
SRAM1_A3: U1.AD24 U1_SMB.4 | length 778.5
  Top Layer w7.87: U1.AD24@1937.01,1062.99 v1(1956.69,1043.31)
  MidLayer1 w5: v1(1956.69,1043.31) 2078.74,1043.31 2090.55,1043.31 2192.91,1043.31 2413.39,822.83 v1(2547.24,822.83)
  Bottom Layer w5: U1_SMB.4@2478.43,822.84 v1(2547.24,822.83)
SRAM1_A4: U1.AC24 U1_SMB.5 | length 734.5
  Top Layer w7.87: U1.AC24@1937.01,1102.36 v1(1956.69,1082.68)
  MidLayer1 w5: v1(1956.69,1082.68) 1984.25,1055.12 2078.74,1055.12 2090.55,1055.12 2200.79,1055.12 2401.57,854.33 v1(2523.62,854.33)
  Bottom Layer w5: U1_SMB.5@2478.43,854.33 v1(2523.62,854.33)
SRAM1_A5: U1.AA22 U1_SMB.18 | length 781.8
  Top Layer w7.87: U1.AA22@1858.27,1181.1 v1(1877.96,1161.42)
  MidLayer4 w5: v1(1877.96,1161.42) 1897.64,1141.73 2078.74,1141.73 2090.55,1141.73 2177.17,1141.73 2299.2,1263.77 v1(2523.83,1263.77)
  Bottom Layer w5: U1_SMB.18@2478.44,1263.77 v1(2523.83,1263.77) v1@2527.77,1263.77
SRAM1_A6: U1.AA21 U1_SMB.19 | length 864.7
  Top Layer w7.87: U1.AA21@1818.9,1181.1 v1(1838.59,1161.42)
  MidLayer4 w5: v1(1838.59,1161.42) 1858.27,1181.1 2078.74,1181.1 2090.55,1181.1 2181.1,1181.1 2295.28,1295.28 v1(2547.24,1295.28)
  Bottom Layer w5: U1_SMB.19@2478.43,1295.28 v1(2547.24,1295.28) v1@2551.18,1295.28
SRAM1_A7: U1.W22 U1_SMB.20 | length 775.2
  Top Layer w7.87: U1.W22@1858.27,1259.84 v1(1877.96,1240.16)
  MidLayer4 w5: v1(1877.96,1240.16) 1897.64,1220.47 2078.74,1220.47 2090.55,1220.47 2181.1,1220.47 2287.4,1326.77 v1(2523.83,1326.76)
  Bottom Layer w5: U1_SMB.20@2478.43,1326.77 v1(2523.83,1326.76) v1@2527.77,1326.76
SRAM1_A8: U1.R21 U1_SMB.21 | length 847.9
  Top Layer w7.87: U1.R21@1818.9,1417.32 v1(1838.59,1397.64)
  MidLayer4 w5: v1(1838.59,1397.64) 1858.27,1417.32 2078.74,1417.32 2090.55,1417.32 2125.98,1417.32 2185.04,1358.27 v1(2547.24,1358.27)
  Bottom Layer w5: U1_SMB.21@2472.44,1358.27 U1_SMB.21@2478.43,1358.27 v1(2547.24,1358.27) v1@2551.18,1358.27
SRAM1_A9: U1.N23 U1_SMB.22 | length 731.9
  Top Layer w7.87: U1.N23@1897.64,1496.06 v1(1917.33,1515.75)
  MidLayer4 w5: v1(1917.33,1515.75) 2078.74,1515.75 2090.55,1515.75 2181.1,1515.75 2307.1,1389.75 v1(2523.83,1389.75)
  Bottom Layer w5: U1_SMB.22@2478.43,1389.76 v1(2523.83,1389.75)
